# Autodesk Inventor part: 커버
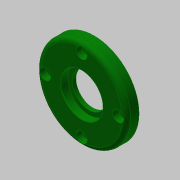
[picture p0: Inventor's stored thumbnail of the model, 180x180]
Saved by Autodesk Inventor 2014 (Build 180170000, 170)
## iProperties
Created: 2019-09
Part Number: 커버
Material: 알루미늄 6061
Document SubType Name: Modeling
Designer: mduedu
Density: 1 g/cm^3
Appearance: 진녹색
Author: mduedu
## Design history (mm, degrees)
sketch "스케치1"
  geometry: C1 r 32 at (0, 0); 1 further point
  constraints: 1 centre point, 1 coincident
  dimensions: "d0" = 64 diameter of C1
extrude "돌출1" new body sketch "스케치1" distance "d1" = 9; taper "d2" = 0 deg
sketch "스케치2"
  geometry: C1 r 21 at (0, 0); 1 further point
  constraints: 1 centre point, 1 coincident
  dimensions: "d3" = 42 diameter of C1
extrude "돌출2" join sketch "스케치2" distance "d4" = 3; taper "d5" = 0 deg
hole "구멍1" diameter "d8" = 24; stored, may be unused: countersink angle "d12" = 90 deg, drill point angle "d14" = 118 deg; dims "d6" = 10, "d7" = 10, "d9" = 6, "d10" = 30, "d11" = 5.2, "d13" = 8
hole "구멍2" diameter "d17" = 37; stored, may be unused: countersink angle "d21" = 90 deg, drill point angle "d23" = 0 deg; dims "d15" = 10, "d16" = 10, "d18" = 6, "d19" = 30, "d20" = 5.2, "d22" = 4
fillet "모깎기1" dims "d24" = 3
fillet "모깎기2" dims "d25" = 3
chamfer "모따기1" distance "d27" = 0.5; stored, may be unused: second distance "d28" = 2, angle "d29" = 30 deg
chamfer "모따기2" distance "d30" = 1; stored, may be unused: second distance "d31" = 2, angle "d32" = 30 deg
sketch "스케치3" dims "d33" = 52
  geometry: 3 further points
  constraints: 2 vertical alignment, 1 coincident, 2 other
hole "구멍3" sketch "스케치3" at (0, 26) diameter "d34" = 4.5; stored, may be unused: countersink angle "d38" = 90 deg, drill point angle "d40" = 0 deg; dims "d35" = 6, "d36" = 8, "d37" = 4.4, "d39" = 4
node "솔리드1"
pattern_circular "원형 패턴1" dims angle "d42" = 360 deg
